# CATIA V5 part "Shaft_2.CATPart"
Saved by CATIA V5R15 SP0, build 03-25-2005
Part number: Shaft_2
Bounding box of the stored display mesh (mm): x -23.8 to 23.8, y -23.8 to 23.8, z 0 to 157
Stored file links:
  E:\#01 CATIA Lecture Materials\#06 DMU\#11 DMU Page01 KIN EX11\Shaft_2.CATPart
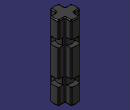
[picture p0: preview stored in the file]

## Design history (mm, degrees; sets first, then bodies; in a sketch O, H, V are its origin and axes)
Body1 (main body)
  Sketch1 on xy-plane, origin (0, 0, 0), H (1, 0, 0), V (0, 1, 0)
    arc A1 centre (0, 0) radius 23.8 from (21.9289, -9.25) to (21.9289, 9.25) ccw
    line L1 (-21.9289, 9.25) -> (-9.25, 9.25)
    line L2 (21.9289, -9.25) -> (9.25, -9.25)
    line L3 (9.25, 21.9289) -> (9.25, 9.25)
    line L4 (-9.25, -21.9289) -> (-9.25, -9.25)
    point P4 (-9.25, -21.9289)
    arc A2 centre (0, 0) radius 23.8 from (-9.25, -21.9289) to (9.25, -21.9289) ccw
    point P6 (-21.9289, 9.25)
    arc A3 centre (0, 0) radius 23.8 from (-21.9289, 9.25) to (-21.9289, -9.25) ccw
    point P8 (9.25, 21.9289)
    arc A4 centre (0, 0) radius 23.8 from (9.25, 21.9289) to (-9.25, 21.9289) ccw
    point P9 (-9.25, 9.25)
    line L5 (9.25, 9.25) -> (21.9289, 9.25)
    line L6 (9.25, -9.25) -> (9.25, -21.9289)
    line L7 (-9.25, 9.25) -> (-9.25, 21.9289)
    point P12 (-9.25, -9.25)
    line L8 (-9.25, -9.25) -> (-21.9289, -9.25)
    radius A1 = 23.8
    distance L1 L2 = 18.5
    distance H L1 = 9.25
    distance L3 L4 = 18.5
    distance V L3 = 9.25
    horizontal: L1 H, L2 H, L5 H, L8 H
    vertical: L3 V, L4 V, L6 V, L7 V
    coincidence: A1 P4, A1 A2, A1 P6, A1 A3, A1 P8, A1 A4, L4 P9, L1 L5, L3 L6, L2 P12, L4 L7, L2 L8
  Pad1: profile Sketch1, direction (0, 0, 1), length 157
  Fillet1: radius 2, on edge [face of Pad1 | face of Pad1] (x4)
  Fillet2: radius 2, on face of Pad1 (x2)
  Sketch2 on zx-plane, origin (0, 0, 0), H (-1, 0, 0), V (0, 0, 1)
    line L1 (14.6694, 50) -> (34.6694, 50)
    line L2 (34.6694, 50) -> (34.6694, 35)
    line L3 (34.6694, 35) -> (14.6694, 35)
    line L4 (14.6694, 35) -> (14.6694, 50)
    line L5 (14.6694, 122) -> (34.6694, 122)
    line L6 (34.6694, 122) -> (34.6694, 107)
    line L7 (34.6694, 107) -> (14.6694, 107)
    line L8 (14.6694, 107) -> (14.6694, 122)
    point P7 (34.6694, 107)
    reference intersected line E1 (-23.8, 157) -> (23.8, 157) from end face of Pad1
    reference intersected line E2 through (9.25, 0) direction (0, 1) from face of Pad1 from Sketch1.L4
    distance L1 L3 = 15
    length L6 = 15
    distance L3 H = 35
    distance L5 E1 = 35
    distance L4 L2 = 20
    distance L8 E2 = 5.4194
    horizontal: L1 H, L3 H, L5 H, L7 H
    vertical: L2 V, L4 V, L6 V, L8 V
    coincidence: P7 L2, L4 L8
  Groove1: profile Sketch2, axis Sketch2.V, angle 360
  Fillet3: radius 2, on edge [face of Pad1 from Sketch1.A4 | face of Pad1 from Sketch1.L3] (x3); edge [face of Pad1 from Sketch1.L5 | face of Pad1 from Sketch1.A1] (x3); edge [face of Pad1 from Sketch1.A3 | face of Pad1 from Sketch1.L1] (x3); edge [face of Pad1 from Sketch1.L7 | face of Pad1 from Sketch1.A4] (x3); edge [face of Pad1 from Sketch1.L8 | face of Pad1 from Sketch1.A3] (x3); edge [face of Pad1 from Sketch1.A2 | face of Pad1 from Sketch1.L4] (x3); edge [face of Pad1 from Sketch1.L6 | face of Pad1 from Sketch1.A2] (x3); edge [face of Pad1 from Sketch1.A1 | face of Pad1 from Sketch1.L2] (x3)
